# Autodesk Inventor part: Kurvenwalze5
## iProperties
Created: 2004-10
Part Number: Kurvenwalze5
Material: .
Document SubType Name: Modeling
Designer: RSC
Manufacturer: Standard
Standards Organization: Custom
Kanten: brechen
Oberflächen: Ra 3,2
Radien: 2
Toleranzen: ISO 2768 - m
Author: RSC
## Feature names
1. Extrusion1
2. Extrusion2
